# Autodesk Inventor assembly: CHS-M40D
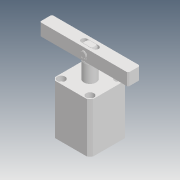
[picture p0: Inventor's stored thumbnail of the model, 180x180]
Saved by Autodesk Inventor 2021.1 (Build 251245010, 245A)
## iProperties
Created: 2019-04
Part Number: CHS-M40D
Description: STEP AP203
Document SubType Name: Assembly
Designer: user
Title: chs-m40d_asm.STEP
Revision Number: ÈÎºÎ
Sending System: SolidWorks 2017
Preprocessor: SwSTEP 2.0
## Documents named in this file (6)
- D:\Vault_2016\Projekty\Clamptek\Hydraulic\CHS\CHS-40\Inventor\CHS-M40D\CHS-M40D.iam
- D:\Vault_2016\Projekty\Clamptek\Hydraulic\CHS\CHS-40\Inventor\CHS-M40D\CHS-40D-02_3.ipt
- D:\Vault_2016\Projekty\Clamptek\Hydraulic\CHS\CHS-40\Inventor\CHS-M40D\CHS-40D-01_4.ipt
- D:\Vault_2016\Projekty\Clamptek\Hydraulic\CHS\CHS-40\Inventor\CHS-M40D\XIAO.ipt
- D:\Vault_2016\Projekty\Clamptek\Hydraulic\CHS\CHS-40\Inventor\CHS-M40D\12ÖáÓÃµ²È¦.ipt
- D:\Vault_2016\Projekty\Clamptek\Hydraulic\CHS\CHS-40\Inventor\CHS-M40D\CHS-M40BT.ipt
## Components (6 placed, 6 different names)
1. CHS-40D-02_3_1
2. CHS-40D-01_4_2
3. XIAO_3
4. 12ÖáÓÃµ²È¦_4
5. 12ÖáÓÃµ²È¦_5
6. CHS-M40BT_6
